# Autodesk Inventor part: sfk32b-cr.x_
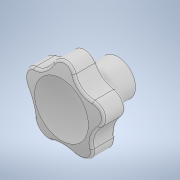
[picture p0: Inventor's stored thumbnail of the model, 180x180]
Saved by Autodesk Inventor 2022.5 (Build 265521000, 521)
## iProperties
Created: 2023-06
Part Number: sfk32b-cr.x_
Material: Generic
Document SubType Name: Modeling
Designer: ImaoCorp
Density: 1 g/cm^3
Appearance: Default
Sending System: SOLIDWORKS 2021-2021301
MC: AMD64
MC_MODEL: Intel64 Family 6 Model 60 Stepping 3, GenuineIntel
OS: Windows_NT
FRU: Parasolid Version 32.1, build 255,  1- 1-2021
FORMAT: text
GUISE: transmit
KEY: sfk32b-cr
FILE: sfk32b-cr.x_t
DATE: Thu Jun 15 16:08:59 2023
Author: ImaoCorp
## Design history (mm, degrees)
feature "Base1"
node "ソリッド1"
